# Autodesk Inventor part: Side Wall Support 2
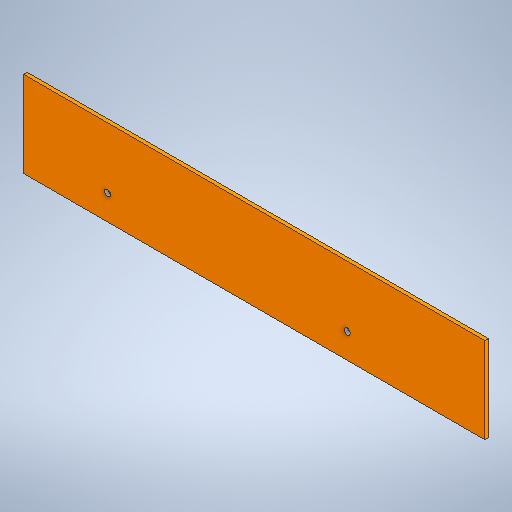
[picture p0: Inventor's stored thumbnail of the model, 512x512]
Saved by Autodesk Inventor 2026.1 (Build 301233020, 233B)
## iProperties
Created: 2026-11
Part Number: Side Wall Support 2
Material: Generic
Document SubType Name: Modeling
Designer: hp
Density: 1 g/cm^3
Appearance: Default
Author: hp
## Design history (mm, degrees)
sketch "Sketch1"
  geometry: L1 (0, 0)-(645, 0); L2 (645, 0)-(645, 120); L3 (645, 120)-(0, 120); L4 (0, 120)-(0, 0)
  constraints: 8 end point, 2 parallel, 1 horizontal, 1 perpendicular
  dimensions: "d0" = 645 distance of L3.end L2.end; "d1" = 120 distance of L2.end L1.end
extrude "Extrusion1" new body sketch "Sketch1" distance "d2" = 5; taper "d3" = 0 deg
sketch "Sketch3"
  geometry: 2 further points
hole "Hole2" sketch "Sketch3" at (-452.5, 35), (-117.5, 35) diameter "d11" = 9; stored, may be unused: countersink angle "d15" = 90 deg, drill point angle "d17" = 0 deg; dims "d12" = 6, "d13" = 4, "d14" = 2, "d16" = 8
body "Solid1"
